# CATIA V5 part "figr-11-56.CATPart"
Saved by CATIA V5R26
Part number: Part1
Bounding box of the stored display mesh (mm): x -50 to 50, y -100 to 150, z -20 to 9.95
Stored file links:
  D:\_Deepak\CATIA\CATIA V5-6R2016_Deepak\Resources\Part files\Partfiles\c11_catia_v5_6r2016_prt\figr-11-56.CATPart
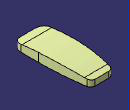
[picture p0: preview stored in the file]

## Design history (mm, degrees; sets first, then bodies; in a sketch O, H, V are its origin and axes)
Set1
  Extrude1: Element1 Sketch2, Lim1 50, Lim2 50, Direction yz-plane
  Sketch1 on xy-plane, origin (0, 0, 0), H (1, 0, 0), V (0, 1, 0)
    arc A1 centre (25, -75) radius 25 from (25, -100) to (50, -75) ccw
    line L1 (50, -75) -> (50, -15)
    point P4 (50, -15)
    arc A2 centre (-950, -15) radius 1000 from (50, -15) to (38.3367, 137.2843) ccw
    line L2 (23.5117, 150) -> (-23.5117, 150)
    line L3 (25, -100) -> (-25, -100)
    arc A3 centre (-25, -75) radius 25 from (-25, -100) to (-50, -75) cw
    line L4 (-50, -75) -> (-50, -15)
    point P9 (-50, -15)
    arc A4 centre (950, -15) radius 1000 from (-50, -15) to (-38.3367, 137.2843) cw
    reference projected line E1 (-50, -100) -> (50, -100) from edge of Extrude1
    axis line L5 (0, 170.4214) -> (0, -120.6595)
    point P11 (0, 170.4214)
    reference projected line E2 (50, -70) -> (50, 129.9971) from edge of Extrude1
    reference projected line E3 (-50, 129.9971) -> (-50, -70) from edge of Extrude1
    reference projected line E4 (-50, -100) -> (50, -100) from edge of Extrude1
    reference projected line E5 (50, 150) -> (-50, 150) from edge of Extrude1
    arc A5 centre (-23.5117, 135) radius 15 from (-38.3367, 137.2843) to (-23.5117, 150) cw
    arc A6 centre (23.5117, 135) radius 15 from (38.3367, 137.2843) to (23.5117, 150) ccw
    distance E4 P4 = 85
    radius A2 = 1000
    radius A5 = 15
    radius A6 = 15
    radius A1 = 25
    radius A3 = 25
    radius A4 = 1000
    tangency: L1 A1, A2 L1, L3 A1, A3 L3, A4 L4, L5 A3, A5 L2, A5 A4, A6 A2, A6 L2, A3 L4
    horizontal: L2 H
    coincidence: L3 E1, P11 V, L1 E2, L4 E3, L2 E5
    symmetry: P4 P9 L5
  Extrude2: Element1 Sketch1, Lim1 50, Lim2 20, Direction xy-plane
  Intersect1: ToIntersect1 Extrude1, ToIntersect2 Extrude2
  Split1: ToCut Extrude2, Cutting Extrude1
  Trim1: Trimmed (Extrude1; Split1)
Body1 (main body)
  Sketch2 on yz-plane, origin (0, 0, 0), H (0, 1, 0), V (0, 0, 1)
    point P1 (-100, 0)
    line L1 (-100, 0) -> (-70, 3.8724)
    point P2 (-70, 3.8724)
    arc A1 centre (26.0141, -739.9564) radius 750 from (-70, 3.8724) to (129.9971, 2.8003) cw
    point P4 (129.9971, 2.8003)
    line L2 (129.9971, 2.8003) -> (150, 0)
    point P5 (150, 0)
    distance P1 P5 = 250
    distance P1 O = 100
    radius A1 = 750
    distance P2 P4 = 200
    distance P2 V = 70
    coincidence: P1 H, P5 H
    tangency: A1 L1, L2 A1
  ThickSurface1: BotOffset 0, Surface Extrude1, TopOffset 5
